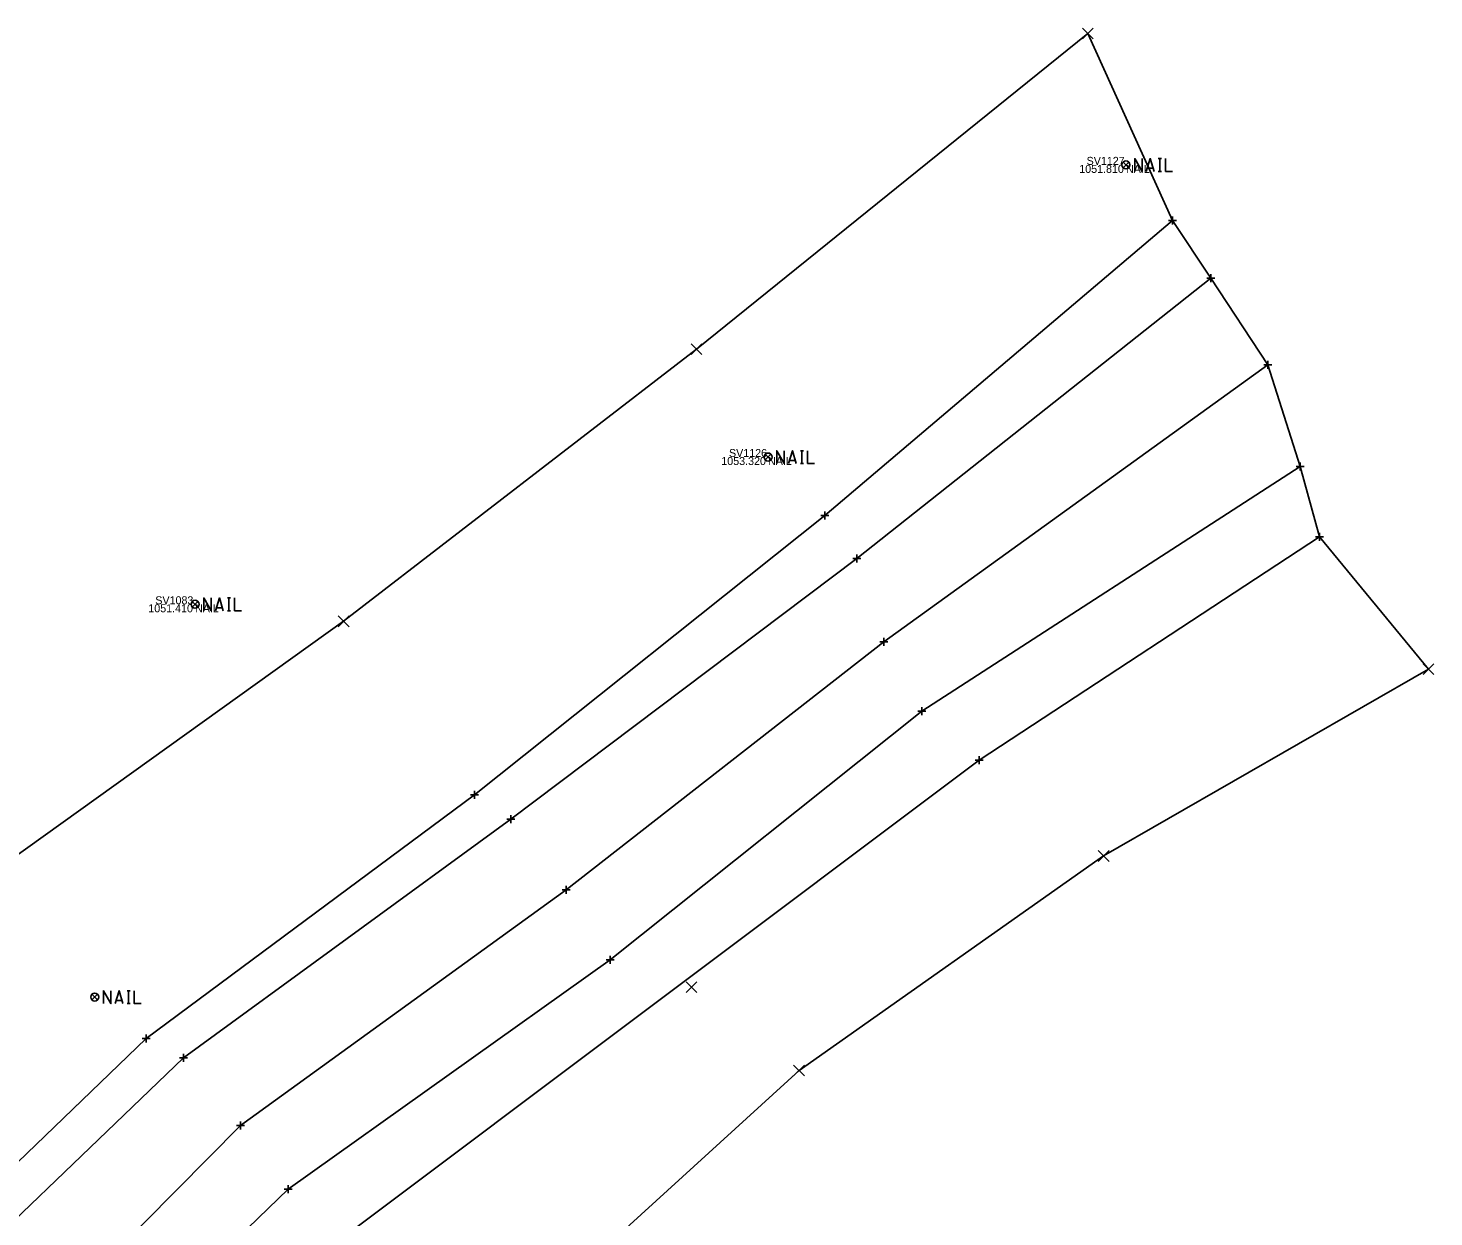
# Model space of a CAD drawing. Extents: x 1620404 to 1621386, y 607070 to 607748.
# Drawn here: x 1621209.9 to 1621385.5, y 607599.8 to 607748.3 of the extents above; entities that cross this region are included whole.
import ezdxf

# ---------------------------------------------------------------- set-up
doc = ezdxf.new("R2010")
doc.units = 0
for name, color, linetype in [('BD_X_Building', 7, 'Continuous'), ('Default', 7, 'Continuous'), ('DR_X_Elev_Flow', 7, 'Continuous'), ('PV_X_Curb', 7, 'Continuous'), ('SN_X_Public', 7, 'Continuous'), ('SV_P_Control_Cells_Set', 7, 'Continuous'), ('SV_X_Shot_Marker', 7, 'Continuous'), ('UT_X_Gas_Cells', 7, 'Continuous'), ('UT_X_Sanitary_Cells', 7, 'Continuous'), ('UT_X_Water', 7, 'Continuous')]:
    doc.layers.add(name, color=color, linetype=linetype)

msp = doc.modelspace()

# ---------------------------------------------------------------- linework, layer by layer
at = {"layer": 'Default'}
msp.add_lwpolyline([(1621193.69, 607508.45), (1621263.9, 607579.48), (1621306.2, 607618.05), (1621344.27, 607644.84), (1621384.87, 607668.18), (1621371.23, 607684.72), (1621368.83, 607693.52), (1621364.8, 607706.19), (1621357.67, 607717.03), (1621352.88, 607724.24), (1621342.29, 607747.61), (1621293.38, 607708.17), (1621249.3, 607674.16), (1621205.39, 607642.75)], dxfattribs=at)
at = {"layer": 'DR_X_Elev_Flow'}
for p, q in [((1621346.71, 607731.54), (1621347.41, 607730.84)), ((1621346.71, 607730.84), (1621347.41, 607731.54)), ((1621301.98, 607695.04), (1621302.68, 607694.34)), ((1621301.98, 607694.34), (1621302.68, 607695.04)), ((1621230.38, 607676.64), (1621231.08, 607675.94)), ((1621230.38, 607675.94), (1621231.08, 607676.64)), ((1621217.84, 607627.56), (1621218.54, 607626.86)), ((1621217.84, 607626.86), (1621218.54, 607627.56))]:
    msp.add_line(p, q, dxfattribs=at)
for points in [[(1621348.15, 607730.38), (1621348.15, 607731.98), (1621349.09, 607730.38), (1621349.09, 607731.98)], [(1621349.6, 607730.38), (1621350.1, 607731.98), (1621350.59, 607730.38)], [(1621351.1, 607731.98), (1621351.5, 607731.98)], [(1621351.3, 607730.38), (1621351.3, 607731.98)], [(1621352, 607731.98), (1621352, 607730.38), (1621352.87, 607730.38)], [(1621350.47, 607730.76), (1621349.72, 607730.76)], [(1621351.1, 607730.38), (1621351.5, 607730.38)], [(1621303.42, 607693.88), (1621303.42, 607695.48), (1621304.36, 607693.88), (1621304.36, 607695.48)], [(1621304.87, 607693.88), (1621305.37, 607695.48), (1621305.86, 607693.88)], [(1621306.37, 607695.48), (1621306.77, 607695.48)], [(1621306.57, 607693.88), (1621306.57, 607695.48)], [(1621307.27, 607695.48), (1621307.27, 607693.88), (1621308.14, 607693.88)], [(1621305.74, 607694.26), (1621304.99, 607694.26)], [(1621306.37, 607693.88), (1621306.77, 607693.88)], [(1621231.82, 607675.48), (1621231.82, 607677.08), (1621232.76, 607675.48), (1621232.76, 607677.08)], [(1621233.27, 607675.48), (1621233.77, 607677.08), (1621234.26, 607675.48)], [(1621234.14, 607675.86), (1621233.39, 607675.86)], [(1621234.77, 607677.08), (1621235.17, 607677.08)], [(1621234.77, 607675.48), (1621235.17, 607675.48)], [(1621234.97, 607675.48), (1621234.97, 607677.08)], [(1621235.67, 607677.08), (1621235.67, 607675.48), (1621236.54, 607675.48)], [(1621219.28, 607626.4), (1621219.28, 607628), (1621220.22, 607626.4), (1621220.22, 607628)], [(1621220.73, 607626.4), (1621221.23, 607628), (1621221.72, 607626.4)], [(1621222.23, 607628), (1621222.63, 607628)], [(1621222.43, 607626.4), (1621222.43, 607628)], [(1621223.13, 607628), (1621223.13, 607626.4), (1621224, 607626.4)], [(1621221.6, 607626.78), (1621220.85, 607626.78)], [(1621222.23, 607626.4), (1621222.63, 607626.4)]]:
    msp.add_lwpolyline(points, dxfattribs=at)
for centre in [(1621347.06, 607731.19), (1621302.33, 607694.69), (1621230.73, 607676.29), (1621218.19, 607627.21)]:
    msp.add_circle(centre, 0.5, dxfattribs=at)
at = {"layer": 'PV_X_Curb'}
msp.add_lwpolyline([(1621098.26, 607460.62), (1621131.78, 607496.09), (1621163.7, 607535.15), (1621204.3, 607578.78), (1621236.39, 607611.18), (1621277.1, 607640.63), (1621316.81, 607671.58), (1621364.8, 607706.19)], dxfattribs=at)
at = {"layer": 'SN_X_Public'}
for p, q in [((1621352.88, 607724.74), (1621352.88, 607723.74)), ((1621352.38, 607724.24), (1621353.38, 607724.24)), ((1621352.88, 607724.24), (1621352.88, 607724.24)), ((1621357.17, 607717.03), (1621358.17, 607717.03)), ((1621357.67, 607717.53), (1621357.67, 607716.53)), ((1621357.67, 607717.03), (1621357.67, 607717.03)), ((1621364.3, 607706.19), (1621365.3, 607706.19)), ((1621364.8, 607706.69), (1621364.8, 607705.69)), ((1621364.8, 607706.19), (1621364.8, 607706.19)), ((1621368.33, 607693.52), (1621369.33, 607693.52)), ((1621368.83, 607694.02), (1621368.83, 607693.02)), ((1621368.83, 607693.52), (1621368.83, 607693.52)), ((1621309.41, 607687.87), (1621309.41, 607686.87)), ((1621308.91, 607687.37), (1621309.91, 607687.37)), ((1621309.41, 607687.37), (1621309.41, 607687.37)), ((1621370.73, 607684.72), (1621371.73, 607684.72)), ((1621371.23, 607685.22), (1621371.23, 607684.22)), ((1621371.23, 607684.72), (1621371.23, 607684.72)), ((1621313.41, 607682.52), (1621313.41, 607681.52)), ((1621312.91, 607682.02), (1621313.91, 607682.02)), ((1621313.41, 607682.02), (1621313.41, 607682.02)), ((1621316.81, 607672.08), (1621316.81, 607671.08)), ((1621316.31, 607671.58), (1621317.31, 607671.58)), ((1621316.81, 607671.58), (1621316.81, 607671.58)), ((1621321.56, 607663.42), (1621321.56, 607662.42)), ((1621321.06, 607662.92), (1621322.06, 607662.92)), ((1621321.56, 607662.92), (1621321.56, 607662.92)), ((1621328.23, 607656.81), (1621329.23, 607656.81)), ((1621328.73, 607657.31), (1621328.73, 607656.31)), ((1621328.73, 607656.81), (1621328.73, 607656.81)), ((1621265.66, 607653), (1621265.66, 607652)), ((1621265.16, 607652.5), (1621266.16, 607652.5)), ((1621265.66, 607652.5), (1621265.66, 607652.5)), ((1621269.67, 607649.45), (1621270.67, 607649.45)), ((1621270.17, 607649.95), (1621270.17, 607648.95)), ((1621270.17, 607649.45), (1621270.17, 607649.45)), ((1621276.6, 607640.63), (1621277.6, 607640.63)), ((1621277.1, 607641.13), (1621277.1, 607640.13)), ((1621277.1, 607640.63), (1621277.1, 607640.63)), ((1621282.09, 607631.86), (1621283.09, 607631.86)), ((1621282.59, 607632.36), (1621282.59, 607631.36)), ((1621282.59, 607631.86), (1621282.59, 607631.86)), ((1621224.12, 607622.05), (1621225.12, 607622.05)), ((1621224.62, 607622.55), (1621224.62, 607621.55)), ((1621224.62, 607622.05), (1621224.62, 607622.05)), ((1621228.77, 607619.63), (1621229.77, 607619.63)), ((1621229.27, 607620.13), (1621229.27, 607619.13)), ((1621229.27, 607619.63), (1621229.27, 607619.63)), ((1621235.89, 607611.18), (1621236.89, 607611.18)), ((1621236.39, 607611.68), (1621236.39, 607610.68)), ((1621236.39, 607611.18), (1621236.39, 607611.18)), ((1621242.36, 607603.73), (1621242.36, 607602.73)), ((1621241.86, 607603.23), (1621242.86, 607603.23)), ((1621242.36, 607603.23), (1621242.36, 607603.23))]:
    msp.add_line(p, q, dxfattribs=at)
at = {"layer": 'SV_X_Shot_Marker'}
for p, q in [((1621341.62, 607746.94), (1621342.96, 607748.28)), ((1621341.62, 607748.28), (1621342.96, 607746.94)), ((1621292.71, 607707.5), (1621294.05, 607708.84)), ((1621292.71, 607708.84), (1621294.05, 607707.5)), ((1621248.63, 607673.49), (1621249.97, 607674.83)), ((1621248.63, 607674.83), (1621249.97, 607673.49)), ((1621384.2, 607667.51), (1621385.54, 607668.85)), ((1621384.2, 607668.85), (1621385.54, 607667.51)), ((1621343.6, 607644.17), (1621344.94, 607645.51)), ((1621343.6, 607645.51), (1621344.94, 607644.17)), ((1621292.1, 607627.78), (1621293.44, 607629.12)), ((1621292.1, 607629.12), (1621293.44, 607627.78)), ((1621305.53, 607617.38), (1621306.87, 607618.72)), ((1621305.53, 607618.72), (1621306.87, 607617.38))]:
    msp.add_line(p, q, dxfattribs=at)
at = {"layer": 'UT_X_Gas_Cells'}
for points in [[(1621088.42, 607469.58), (1621121.71, 607508.87), (1621152.08, 607547.5), (1621190.16, 607588.87), (1621224.62, 607622.05), (1621265.66, 607652.5), (1621309.41, 607687.37), (1621352.88, 607724.24)], [(1621112.46, 607448.56), (1621147.34, 607478.88), (1621178.32, 607522.05), (1621214.26, 607564.83), (1621247.99, 607596.27), (1621328.73, 607656.81), (1621371.23, 607684.72)]]:
    msp.add_lwpolyline(points, dxfattribs=at)
at = {"layer": 'UT_X_Sanitary_Cells'}
for points in [[(1621091.98, 607467.57), (1621125.27, 607503.64), (1621155.57, 607543.55), (1621194.23, 607585.96), (1621229.27, 607619.63), (1621270.17, 607649.45), (1621313.41, 607682.02), (1621357.67, 607717.03)], [(1621101.67, 607453.07), (1621137.45, 607489.83), (1621169.81, 607529.9), (1621212.19, 607574.07), (1621242.36, 607603.23), (1621282.59, 607631.86), (1621321.56, 607662.92), (1621368.83, 607693.52)]]:
    msp.add_lwpolyline(points, dxfattribs=at)

# ---------------------------------------------------------------- texts
at = {"layer": 'BD_X_Building'}
for p in [(1621347.06, 607730.19), (1621302.33, 607693.69), (1621230.73, 607675.29)]:
    msp.add_text('NAIL', height=1, dxfattribs=at).set_placement(p)
at = {"layer": 'SV_P_Control_Cells_Set'}
for s, p in [('SV1127', (1621342.14, 607731.19)), ('SV1126', (1621297.45, 607694.69)), ('SV1083', (1621225.76, 607676.29))]:
    msp.add_text(s, height=1, dxfattribs=at).set_placement(p)
at = {"layer": 'UT_X_Water'}
for s, p in [('1051.810', (1621341.22, 607730.19)), ('1053.320', (1621296.49, 607693.69)), ('1051.410', (1621224.89, 607675.29))]:
    msp.add_text(s, height=1, dxfattribs=at).set_placement(p)

doc.saveas('drawing.dxf')
